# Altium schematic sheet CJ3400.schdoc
size 127 x 101 mm
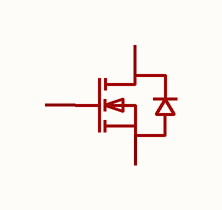
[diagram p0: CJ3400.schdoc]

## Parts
Q?  cj3400  [SOT-23_L2.9-W1.3-P1.90-LS2.4-BR]  (value not drawn)

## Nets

Not connected (* = marked no-connect by the designer): Q? 1(G) 2(S) 3(D)

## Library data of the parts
Q? = cj3400: 数量:1个N沟道;漏源电压(Vdss):30V;连续漏极电流(Id):5.8A;导通电阻(RDS(on)):52mΩ@2.5V;耗散功率(Pd):350mW;阈值电压(Vgs(th)):1.4V;; Manufacturer: CJ(江苏长电/长晶); AddInBom: yes; ModelId: c62791f0466c4ae2a892c056b845b0ca; ModelName: SOT-23-3P_L2.9-W1.3-H1.0-LS2.4-P0.95; ModelTransform: 98.64468,114.173,0,180,0,0,0.001,-0.002,0; Number: 1个N沟道; Drain to Source Voltage: 30V; Current - Continuous Drain(Id): 5.8A; Pd - Power Dissipation: 350mW; Gate Threshold Voltage (Vgs(th)): 1.4V; Input Capacitance(Ciss): 1.05nF; Reverse Transfer Capacitance (Crss@Vds): 77pF; Type: N沟道; Output Capacitance(Coss): 66pF; Vgs: ±12V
